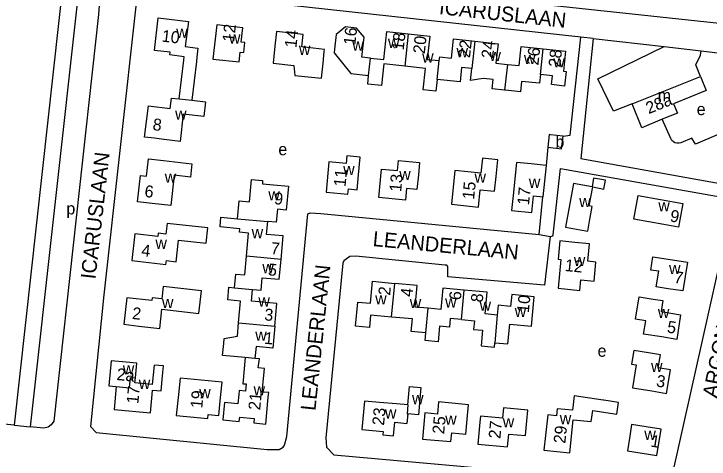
# Model space of a CAD drawing. Extents: x 161773 to 163836, y 384796 to 386521.
# Drawn here: x 162231.1 to 162464.1, y 385728.3 to 385877.5 of the extents above; entities that cross this region are included whole.
import ezdxf

# ---------------------------------------------------------------- set-up
doc = ezdxf.new("R2010")
doc.units = 0
for name, color, linetype in [('BLT_Basislijn', 7, 'Continuous'), ('BLT_Bebouwing', 7, 'Continuous'), ('BLT_Centroide', 7, 'Continuous'), ('BLT_Huisnummer', 7, 'Continuous'), ('BLT_Onderverdeling_panden', 7, 'Continuous'), ('BLT_Straatnaam', 7, 'Continuous')]:
    doc.layers.add(name, color=color, linetype=linetype)

msp = doc.modelspace()

# ---------------------------------------------------------------- linework, layer by layer
at = {"layer": 'BLT_Basislijn'}
for p, q in [((162425.24, 385869.19), (162421.09, 385869.66)), ((162425.24, 385869.19), (162449.03, 385866.51)), ((162449.03, 385866.51), (162461.42, 385865.06)), ((162461.42, 385865.06), (162472.97, 385863.71)), ((162410.02, 385832.77), (162409.42, 385826.72)), ((162411.84, 385803.43), (162414.31, 385825.68)), ((162414.31, 385825.68), (162472.4, 385815.29)), ((162407.18, 385803.55), (162408.38, 385816.2)), ((162451.9, 385723.59), (162472.4, 385815.29)), ((162411.71, 385803.14), (162411.84, 385803.43)), ((162410.77, 385802.94), (162408.86, 385786.56)), ((162410.77, 385802.94), (162411.71, 385803.14)), ((162345.68, 385796.35), (162343.64, 385796.14)), ((162375.57, 385793.31), (162345.68, 385796.35)), ((162341.29, 385793.97), (162335.65, 385735.47)), ((162341.61, 385794.77), (162341.29, 385793.97)), ((162343.64, 385796.14), (162341.61, 385794.77)), ((162376.14, 385793.24), (162375.57, 385793.31)), ((162376.46, 385792.86), (162376.14, 385793.24)), ((162376.47, 385789.42), (162376.46, 385792.86)), ((162408.86, 385786.56), (162376.47, 385789.42)), ((162231.14, 385739.66), (162161.24, 385746.35)), ((162231.14, 385739.66), (162236.52, 385739.12)), ((162335.65, 385735.47), (162335.81, 385732.29)), ((162335.81, 385732.29), (162338.28, 385729.69)), ((162338.28, 385729.69), (162428.37, 385721.76))]:
    msp.add_line(p, q, dxfattribs=at)
for points in [[(162312.67, 385896.24), (162312.77, 385894.67), (162313.69, 385892.54), (162317.19, 385890.56), (162477.99, 385873.28), (162483.44, 385873.42), (162485.48, 385875.36), (162486.1, 385877.57)], [(162262.04, 385890.76), (162249.29, 385892.02), (162248.28, 385892.03), (162247.96, 385891.53), (162231.14, 385739.66)], [(162260.03, 385885.07), (162253.54, 385885.74), (162252.74, 385885.17), (162236.52, 385739.12)], [(162260.03, 385885.07), (162259.38, 385877.3), (162244.41, 385741.03), (162243.6, 385739.8), (162242.55, 385739), (162241.05, 385738.73), (162236.52, 385739.12)], [(162421.09, 385869.66), (162280.08, 385885.14), (162276.18, 385885.47), (162273.68, 385884.97), (162272.15, 385882.05), (162261.23, 385783.38), (162256.71, 385739.19), (162258.62, 385737.22), (162315.92, 385731.49), (162319.96, 385731.49), (162321.33, 385732.35), (162321.81, 385732.99), (162322.55, 385735.84), (162329.57, 385810.51), (162330.36, 385810.78), (162333.99, 385810.59), (162407.18, 385803.55)], [(162415.13, 385836.48), (162417.57, 385836.85), (162421.09, 385869.66)], [(162425.24, 385869.19), (162421.12, 385828.99), (162473.35, 385819.69)], [(162438.26, 385847.32), (162432.09, 385844.83), (162426.82, 385855.73), (162449.03, 385866.51)], [(162461.25, 385856.5), (162459.63, 385860.42), (162461.19, 385863.58), (162461.42, 385865.06)], [(162467.14, 385837.07), (162459.5, 385833.85), (162458.3, 385835.79), (162454.61, 385834.3), (162454.01, 385834.13), (162453.31, 385834.12), (162452.62, 385834.3), (162452.1, 385834.6), (162451.61, 385835.06), (162451.23, 385835.71), (162448.41, 385842.14)], [(162407.18, 385803.55), (162407.8, 385803.49), (162410.77, 385802.94)]]:
    msp.add_lwpolyline(points, dxfattribs=at)
at = {"layer": 'BLT_Bebouwing'}
for p, q in [((162286.42, 385848.95), (162287.98, 385862.01)), ((162373.64, 385861.79), (162373.78, 385863.11)), ((162292.26, 385861.5), (162290.71, 385848.51)), ((162409.42, 385826.72), (162408.38, 385816.2)), ((162306.04, 385808.85), (162316.13, 385807.93)), ((162348.57, 385747.76), (162347.66, 385738.28)), ((162353.57, 385747.31), (162348.57, 385747.76)), ((162359.3, 385746.8), (162353.57, 385747.31)), ((162363.14, 385746.44), (162359.3, 385746.8)), ((162363.05, 385743.49), (162362.75, 385740.29)), ((162358.27, 385736.06), (162358.71, 385740.7)), ((162358.71, 385740.7), (162362.75, 385740.29)), ((162347.66, 385738.28), (162354.83, 385737.59)), ((162354.83, 385737.59), (162354.71, 385736.4)), ((162354.71, 385736.4), (162358.27, 385736.06))]:
    msp.add_line(p, q, dxfattribs=at)
for points in [[(162287.98, 385862.01), (162288.12, 385863.12), (162283.37, 385863.69), (162283.48, 385864.61), (162278.14, 385865.25), (162279.44, 385876.12), (162289.53, 385874.92), (162288.52, 385866.48), (162292.76, 385865.98), (162292.43, 385862.94), (162292.26, 385861.5)], [(162308.12, 385864.48), (162308.48, 385867.85), (162307.25, 385867.98), (162307.77, 385872.83), (162299.03, 385873.77), (162297.79, 385862.33), (162306.54, 385861.38), (162306.89, 385864.61), (162308.12, 385864.48)], [(162334.13, 385855.88), (162334.79, 385861.98), (162334.82, 385862.29), (162335.09, 385864.85), (162335.17, 385865.56), (162327.56, 385866.38), (162328.02, 385870.61), (162319.06, 385871.57), (162318.52, 385866.6), (162317.92, 385860.95), (162324.92, 385860.2), (162325.23, 385856.84), (162334.13, 385855.88)], [(162350.61, 385862.64), (162347.7, 385862.96), (162348.43, 385869.61), (162345.94, 385872.72), (162342.19, 385873.13), (162339.03, 385870.6), (162338.49, 385865.63), (162338.36, 385864.46), (162343.97, 385857.46), (162349.96, 385856.8)], [(162350.61, 385862.64), (162355.01, 385862.15), (162356.04, 385871.57), (162363.26, 385870.78)], [(162363.26, 385870.78), (162370.48, 385869.98), (162369.63, 385862.23), (162373.64, 385861.79)], [(162373.78, 385863.11), (162377.7, 385862.68), (162378.41, 385869.08), (162385.54, 385868.31)], [(162385.54, 385868.31), (162393.36, 385867.43), (162392.65, 385860.98), (162396.51, 385860.55)], [(162396.51, 385860.55), (162400.38, 385860.12), (162401.09, 385866.57), (162408.51, 385865.75)], [(162408.51, 385865.75), (162415.97, 385864.93), (162415.23, 385858.23), (162416.16, 385858.13), (162415.62, 385853.27), (162411.29, 385853.75), (162411.62, 385856.69), (162407.56, 385857.14)], [(162362.07, 385859.97), (162355.07, 385860.74), (162354.26, 385853.44), (162349.65, 385853.94), (162349.96, 385856.8)], [(162372.95, 385855.5), (162372.51, 385851.53), (162368.22, 385852), (162369.01, 385859.2), (162362.07, 385859.97)], [(162384.53, 385859.13), (162381.14, 385859.5), (162380.61, 385854.66), (162372.95, 385855.5)], [(162395.56, 385851.92), (162391.4, 385852.38), (162391.73, 385855.46), (162388.39, 385855.82), (162384.08, 385855.11), (162384.53, 385859.13)], [(162407.56, 385857.14), (162407.24, 385854.2), (162401.23, 385854.86), (162400.85, 385851.33), (162395.88, 385851.88), (162395.56, 385851.92)], [(162438.26, 385847.32), (162461.25, 385856.5)], [(162461.25, 385856.5), (162463.15, 385851.78), (162452.16, 385847.37), (162453.46, 385844.19)], [(162290.71, 385848.51), (162295.3, 385847.96), (162294.71, 385843.08), (162287.85, 385843.9), (162286.76, 385834.75), (162281.43, 385835.39), (162281.32, 385835.4), (162278.15, 385835.78), (162274.87, 385836.17), (162276.13, 385846.7), (162283.43, 385845.82), (162283.84, 385849.26), (162286.42, 385848.95)], [(162448.41, 385842.14), (162441.5, 385839.34), (162438.26, 385847.32)], [(162453.46, 385844.19), (162448.41, 385842.14)], [(162415.13, 385836.48), (162410.94, 385836.95), (162410.5, 385837), (162410.02, 385832.77)], [(162410.02, 385832.77), (162414.65, 385832.25), (162415.13, 385836.48)], [(162281.17, 385828.36), (162290.74, 385827.28), (162290.24, 385822.77), (162284.75, 385823.39), (162283.61, 385813.23), (162277.46, 385813.92), (162272.46, 385814.48), (162273.46, 385823.28), (162275.54, 385823.05), (162276.2, 385828.92), (162281.17, 385828.36)], [(162346.6, 385823.51), (162347.17, 385829.45), (162342.68, 385829.87), (162342.44, 385827.39), (162336.67, 385827.93), (162335.7, 385817.72), (162343.03, 385817.02), (162343.2, 385818.81), (162346.13, 385818.53), (162346.6, 385823.51)], [(162392.67, 385823.01), (162393.24, 385828.57), (162388.11, 385829.1), (162387.59, 385824.07), (162378.85, 385824.96), (162377.69, 385813.67), (162386.76, 385812.74), (162387.35, 385818.53), (162392.17, 385818.03), (162392.67, 385823.01)], [(162366.63, 385823.59), (162366.15, 385818.61), (162362.64, 385818.95), (162362.27, 385815.09), (162353.41, 385815.95), (162354.33, 385825.48), (162359.67, 385824.97), (162360, 385828.38), (162367.02, 385827.7), (162366.63, 385823.59)], [(162409.42, 385826.72), (162404.45, 385827.21), (162399.49, 385827.7), (162398.39, 385816.59), (162397.9, 385811.62), (162404.65, 385810.95), (162405.2, 385816.52), (162408.38, 385816.2)], [(162306.04, 385808.85), (162306.59, 385814.83), (162310, 385814.52), (162310.68, 385822.03), (162314.41, 385821.69), (162314.35, 385820.54), (162318.12, 385820.2), (162323.09, 385819.75), (162322.37, 385811.76), (162319.38, 385812.03), (162318.99, 385807.72), (162316.13, 385807.93)], [(162424.02, 385808.01), (162424.91, 385812.93), (162423.92, 385813.11), (162425.07, 385819.47), (162428.83, 385818.79), (162429.36, 385821.72), (162425.37, 385822.44), (162424.84, 385819.51), (162418.66, 385820.63), (162416, 385805.96), (162420.92, 385805.07), (162423.4, 385804.62), (162424.02, 385808.01)], [(162453.83, 385806.01), (162448.92, 385806.9), (162438.84, 385808.74), (162440.29, 385816.65), (162455.27, 385813.91), (162453.83, 385806.01)], [(162309.02, 385796.28), (162309.72, 385804.03), (162306.71, 385804.3), (162306.82, 385805.46), (162300.17, 385806.07), (162300.47, 385809.36), (162306.04, 385808.85)], [(162320.6, 385795.21), (162321.33, 385803.06), (162315.73, 385803.57), (162316.13, 385807.93)], [(162285.44, 385794.43), (162286.25, 385801.68), (162295.49, 385800.64), (162296.07, 385805.74), (162282.39, 385807.24), (162282, 385803.68), (162279.43, 385803.97), (162279.31, 385802.93), (162271.64, 385803.8), (162270.63, 385794.83), (162282.03, 385793.55), (162282.17, 385794.8), (162285.44, 385794.43)], [(162421.09, 385788.37), (162425.52, 385787.93), (162426.14, 385794.31), (162423.47, 385794.57), (162424.04, 385800.42), (162419.06, 385800.9), (162414.09, 385801.39), (162413.49, 385795.31), (162414.44, 385795.22), (162413.49, 385785.53)], [(162305, 385785.74), (162305.42, 385790.31), (162308.45, 385790.04), (162309.02, 385796.28)], [(162311.05, 385785.17), (162313.92, 385784.91), (162314.3, 385789.09), (162319.98, 385788.57), (162320.6, 385795.21)], [(162451.86, 385795.04), (162456.8, 385794.27), (162455.3, 385784.63), (162450.36, 385785.4), (162446.39, 385786.02), (162447.2, 385791.25), (162444.52, 385791.66), (162445.21, 385796.08), (162451.86, 385795.04)], [(162357.64, 385775.9), (162350.64, 385776.56), (162350.25, 385772.38), (162345.61, 385772.81), (162346.37, 385780.94), (162350.6, 385780.54), (162351.28, 385787.87), (162358.7, 385787.17)], [(162369.94, 385778.84), (162365.53, 385779.26), (162366.21, 385786.47), (162358.7, 385787.17)], [(162413.49, 385785.53), (162420.75, 385784.82), (162421.09, 385788.37)], [(162293.06, 385777.08), (162293.92, 385784.64), (162281.07, 385786.1), (162280.6, 385781.98)], [(162306.36, 385773.95), (162307.02, 385781.26), (162302.75, 385781.65), (162303.14, 385785.91), (162305, 385785.74)], [(162318.54, 385772.84), (162319.23, 385780.39), (162310.68, 385781.17), (162311.05, 385785.17)], [(162381.97, 385784.95), (162374.79, 385785.63), (162374.12, 385778.45), (162369.94, 385778.84)], [(162393.04, 385776.56), (162388.99, 385776.94), (162389.67, 385784.23), (162381.97, 385784.95)], [(162280.6, 385781.98), (162277.43, 385782.34), (162277.32, 385781.43), (162268.93, 385782.38), (162267.91, 385773.46), (162272.88, 385772.89), (162279.95, 385772.09), (162280.68, 385778.49), (162293.06, 385777.08)], [(162392.32, 385767.31), (162396.65, 385766.9), (162397.27, 385773.51), (162404.55, 385772.82), (162405.01, 385777.72), (162405.47, 385782.7), (162397.92, 385783.41), (162397.55, 385779.44), (162393.35, 385779.83), (162393.04, 385776.56)], [(162445.35, 385781.91), (162448.6, 385781.39), (162448, 385777.72), (162454.55, 385776.66), (162453.22, 385768.42), (162448.28, 385769.22), (162442.14, 385770.21), (162442.85, 385774.62), (162439.39, 385775.18), (162440.6, 385782.68), (162445.35, 385781.91)], [(162369.15, 385770.58), (162364.25, 385771.04), (162364.64, 385775.25), (162357.64, 385775.9)], [(162381.04, 385775.04), (162377.31, 385775.39), (162377.03, 385772.49), (162373.77, 385772.8), (162373.28, 385767.65), (162368.91, 385768.06), (162369.15, 385770.58)], [(162308.61, 385762.3), (162301.01, 385762.99), (162301.38, 385767.03), (162301.53, 385768.72), (162305.96, 385769.5), (162306.36, 385773.95)], [(162381.04, 385775.04), (162385.41, 385774.63), (162385.14, 385771.73), (162388.16, 385771.45), (162387.68, 385766.23), (162392.18, 385765.81), (162392.32, 385767.31)], [(162318.54, 385772.84), (162317.87, 385765.48), (162312.21, 385765.99), (162311.85, 385762.01)], [(162444.9, 385751.13), (162449.84, 385750.34), (162451.11, 385758.27), (162447.07, 385758.92), (162447.77, 385763.29), (162443.8, 385763.93), (162438.87, 385764.72), (162438.12, 385760.09), (162439.67, 385759.84), (162438.43, 385752.17), (162444.9, 385751.13)], [(162308.61, 385762.3), (162307.81, 385753.58), (162308.93, 385753.48), (162308.72, 385751.12), (162306.55, 385751.25), (162306.44, 385750), (162306.14, 385746.82), (162301.67, 385747.25), (162301.12, 385741.46), (162306.61, 385740.94), (162306.74, 385742.41), (162311.59, 385741.95)], [(162311.59, 385741.95), (162311.45, 385740.41), (162315.47, 385740.03), (162316.2, 385747.81), (162316.41, 385750), (162316.46, 385750.58), (162314.97, 385750.73), (162314.26, 385750.79), (162315.01, 385758.7), (162312.99, 385758.89), (162313.37, 385761.87), (162311.85, 385762.01)], [(162271.78, 385755.5), (162272.24, 385760.42), (162268.65, 385760.75), (162263.67, 385761.22), (162262.89, 385752.84), (162265.38, 385752.61)], [(162277.38, 385750), (162277.52, 385751.45), (162280.46, 385751.18), (162280.92, 385756.16), (162281.24, 385759.53), (162278.04, 385759.83), (162277.43, 385753.3), (162271.62, 385753.84), (162271.78, 385755.5)], [(162296.05, 385741.88), (162296.19, 385743.24), (162299.72, 385742.87), (162300.23, 385747.85), (162300.42, 385750), (162300.86, 385754.04), (162286.74, 385755.48), (162286.18, 385750), (162285.46, 385742.97), (162296.05, 385741.88)], [(162265.38, 385752.61), (162264.66, 385744.94), (162276.8, 385743.81), (162277.38, 385750)], [(162363.14, 385746.44), (162363.7, 385752.61), (162367.47, 385752.27), (162366.65, 385743.15), (162363.05, 385743.49)], [(162377.8, 385737.12), (162382.49, 385736.69), (162382.94, 385741.67), (162383.39, 385746.53), (162373.42, 385747.45), (162373.05, 385743.38), (162368.85, 385743.77), (162368.5, 385740.02), (162368.05, 385735.04), (162377.53, 385734.17), (162377.8, 385737.12)], [(162428.8, 385748.05), (162428.62, 385748.08), (162418.83, 385749.54), (162418.31, 385744.65), (162413.2, 385745.19), (162412.94, 385742.79), (162409.98, 385743.1), (162409.26, 385736.27), (162408.73, 385731.3), (162417.39, 385730.38), (162418.57, 385741.5), (162424.61, 385740.86), (162425.16, 385744.56), (162433.15, 385743.35), (162433.74, 385747.31), (162428.8, 385748.05)], [(162402.95, 385741.17), (162403.28, 385744.76), (162395.12, 385745.52), (162394.8, 385742.07), (162387.45, 385742.75), (162387.26, 385740.69), (162386.57, 385733.29), (162396.54, 385732.37), (162396.94, 385736.7), (162402.49, 385736.19), (162402.95, 385741.17)], [(162446.6, 385729.53), (162447.97, 385738.36), (162443.03, 385739.13), (162438.13, 385739.89), (162437.53, 385736), (162436.76, 385731.06), (162446.6, 385729.53)]]:
    msp.add_lwpolyline(points, dxfattribs=at)
at = {"layer": 'BLT_Onderverdeling_panden'}
for p, q in [((162363.26, 385870.78), (162362.07, 385859.97)), ((162385.54, 385868.31), (162384.53, 385859.13)), ((162407.56, 385857.14), (162408.51, 385865.75)), ((162349.96, 385856.8), (162350.61, 385862.64)), ((162372.95, 385855.5), (162373.64, 385861.79)), ((162396.51, 385860.55), (162395.56, 385851.92)), ((162286.42, 385848.95), (162290.71, 385848.51)), ((162320.6, 385795.21), (162309.02, 385796.28)), ((162357.64, 385775.9), (162358.7, 385787.17)), ((162305, 385785.74), (162311.05, 385785.17)), ((162381.04, 385775.04), (162381.97, 385784.95)), ((162369.15, 385770.58), (162369.94, 385778.84)), ((162393.04, 385776.56), (162392.32, 385767.31)), ((162306.36, 385773.95), (162318.54, 385772.84))]:
    msp.add_line(p, q, dxfattribs=at)
for points in [[(162311.85, 385762.01), (162308.61, 385762.3)], [(162265.38, 385752.61), (162269.85, 385752.18), (162270.18, 385755.66), (162271.78, 385755.5)], [(162363.14, 385746.44), (162362.86, 385743.51), (162363.05, 385743.49)]]:
    msp.add_lwpolyline(points, dxfattribs=at)

# ---------------------------------------------------------------- texts
at = {"layer": 'BLT_Centroide'}
for s, p in [('w', (162285.45, 385869.42)), ('w', (162303.14, 385867.53)), ('w', (162356.45, 385866.06)), ('w', (162326.59, 385863.72)), ('w', (162344.48, 385865.14)), ('w', (162367.88, 385861.16)), ('w', (162379.42, 385862.92)), ('w', (162390.47, 385861.67)), ('w', (162402.03, 385860.62)), ('w', (162411.86, 385859.53)), ('m', (162446.85, 385848.19)), ('e', (162459.94, 385843.55)), ('w', (162285.08, 385842.02)), ('b', (162412.58, 385832.62)), ('e', (162319.71, 385830.11)), ('w', (162341.42, 385823.44)), ('w', (162360.22, 385821.81)), ('w', (162281.61, 385820.88)), ('w', (162385.45, 385820.91)), ('w', (162403.66, 385819.17)), ('w', (162316.35, 385814.97)), ('w', (162420.53, 385812.72)), ('p', (162248.66, 385810.29)), ('w', (162447.05, 385811.31)), ('w', (162310.75, 385802.28)), ('w', (162278.5, 385798.75)), ('w', (162418.75, 385792.97)), ('w', (162314.34, 385790.59)), ('w', (162450.66, 385790.28)), ('w', (162313, 385779.38)), ('w', (162352.16, 385780.12)), ('w', (162280.68, 385778.88)), ('w', (162363.75, 385778.88)), ('w', (162375.59, 385779.09)), ('w', (162387.14, 385778)), ('w', (162398.92, 385775.91)), ('w', (162446.91, 385775.56)), ('w', (162311.95, 385767.97)), ('e', (162426.71, 385762.6)), ('w', (162267.57, 385756.69)), ('w', (162444.62, 385757.48)), ('w', (162272.91, 385751.81)), ('w', (162311.39, 385749.66)), ('w', (162293.17, 385748.69)), ('w', (162364.51, 385746.71)), ('w', (162355.43, 385741.91)), ('w', (162375.63, 385739.84)), ('w', (162414.03, 385739.97)), ('w', (162394.91, 385738.94)), ('w', (162442.37, 385734.72))]:
    msp.add_text(s, height=4, dxfattribs=at).set_placement(p)
at = {"layer": 'BLT_Huisnummer'}
for s, rotation, p in [('12', 83.8469, (162304.89, 385867.9)), ('10', 353.1873, (162280.46, 385868.2)), ('14', 83.8724, (162325.75, 385865.98)), ('16', 83.7127, (162345.48, 385866.83)), ('18', 83.7186, (162361.7, 385865.11)), ('20', 83.7119, (162368.77, 385863.97)), ('22', 83.7095, (162383.93, 385862.59)), ('24', 83.6912, (162391.67, 385862.38)), ('26', 83.7143, (162406.86, 385860.1)), ('28', 84.1665, (162414.18, 385859.45)), ('28a', 21.9241, (162443.84, 385843.85)), ('8', 353.1783, (162277.42, 385838.55)), ('11', 84.5533, (162342.21, 385819.42)), ('13', 84.5151, (162360.86, 385817.7)), ('6', 353.5657, (162274.69, 385816.16)), ('15', 84.1697, (162385.3, 385815.17)), ('9', 354.793, (162318.16, 385813.74)), ('17', 84.1697, (162403.7, 385813.27)), ('9', 349.6736, (162450.76, 385807.98)), ('7', 354.7275, (162317.03, 385797.04)), ('4', 353.5809, (162273.63, 385796.35)), ('12', 354.4514, (162415.63, 385791.34)), ('5', 354.8019, (162316.11, 385789.9)), ('7', 351.1519, (162452.14, 385787.41)), ('2', 84.6319, (162357.15, 385783)), ('4', 84.6343, (162364.64, 385782.54)), ('6', 84.6358, (162380.87, 385781.43)), ('8', 84.6366, (162388.17, 385780.69)), ('10', 84.6361, (162403.65, 385777.18)), ('2', 353.5004, (162270.53, 385775.28)), ('3', 354.8018, (162314.87, 385774.82)), ('5', 350.7993, (162449.79, 385770.76)), ('1', 354.8056, (162314.84, 385766.97)), ('2a', 354.6531, (162265.38, 385754.82)), ('3', 350.8569, (162446.17, 385752.67)), ('17', 84.6505, (162272.76, 385746.71)), ('19', 85.0314, (162294.2, 385745.23)), ('21', 84.6104, (162313.6, 385744.57)), ('23', 84.4912, (162355.11, 385739.45)), ('25', 84.7454, (162375.27, 385736.58)), ('27', 84.7101, (162394.12, 385735.01)), ('29', 83.9551, (162415.88, 385733.38)), ('1', 351.1506, (162444.29, 385732.53))]:
    msp.add_text(s, height=4, rotation=rotation, dxfattribs=at).set_placement(p)
at = {"layer": 'BLT_Straatnaam'}
for s, rotation, p in [('ICARUSLAAN', 353.7717, (162373.42, 385877.41)), ('ICARUSLAAN', 83.5575, (162258.39, 385788.41)), ('ARGONAUTENLAAN', 78.9636, (162466.74, 385748.55)), ('LEANDERLAAN', 354.644, (162351.2, 385799.69)), ('LEANDERLAAN', 84.0864, (162332.12, 385744.36))]:
    msp.add_text(s, height=5, rotation=rotation, dxfattribs=at).set_placement(p)

doc.saveas('drawing.dxf')
